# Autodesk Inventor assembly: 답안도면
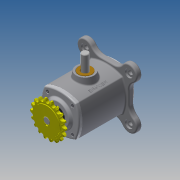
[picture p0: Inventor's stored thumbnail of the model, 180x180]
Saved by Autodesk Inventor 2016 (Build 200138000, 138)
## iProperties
Created: 2016-05
Part Number: 답안도면
Document SubType Name: Assembly
Designer: Administrator
Author: Administrator
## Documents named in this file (11)
- D:\460508V1004\답안도면.iam
- D:\460508V1004\본체.ipt
- D:\460508V1004\커버.ipt
- D:\460508V1004\베어링-6203.ipt
- D:\460508V1004\편심축.ipt
- D:\460508V1004\키5x5.ipt
- D:\460508V1004\스프로킷.ipt
- D:\460508V1004\오일실.ipt
- D:\460508V1004\부시.ipt
- D:\460508V1004\슬라이더.ipt
- D:\460508V1004\M4x0.7x12.ipt
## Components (8 placed, 1 different names)
1. M4x0.7x12:1
2. M4x0.7x12:2
3. M4x0.7x12:3
4. M4x0.7x12:4
5. M4x0.7x12:5
6. M4x0.7x12:6
7. M4x0.7x12:7
8. M4x0.7x12:8
